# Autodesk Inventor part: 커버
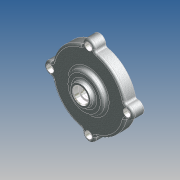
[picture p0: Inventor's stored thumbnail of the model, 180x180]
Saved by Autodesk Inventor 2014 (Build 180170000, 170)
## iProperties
Created: 2012-05
Part Number: 커버
Document SubType Name: 모델링
Designer: SeoGD™
Material: 알루미늄 6061
Appearance: 알루미늄 캐스트
Mass: 72.5671 g
Surface Area: 278.607 cm^2
Volume: 72.5671 cm^3
Density: 1 g/cm^3
변환 표준: STEP AP214IS
파일 이름: C:\Users\SeoGD\Desktop\?쒗뿕\而ㅻ쾭-1.stp
전처리기: Build: 253, Release: 2010 SP1 - Date: Wed 07/29/2009
전송 단위: 밀리미터
불확실성: 0.01
Author: SeoGD™
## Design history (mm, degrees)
sketch "스케치1"
  geometry: L1 (0, 0)-(0, 26); L2 (50, 0)-(50, 15); L3 (50, 15)-(25, 15); L4 (25, 15)-(25, 21); L5 (25, 21)-(15, 21); L6 (15, 21)-(13.66, 26); L7 (13.66, 26)-(10, 26); L8 (50, 0)-(45, 0); L9 (45, 0)-(45, 10); L10 (45, 10)-(14.5, 10); L11 (14.5, 10)-(13.266, 3); L12 (13.266, 3)-(11, 3); L13 (11, 3)-(11, 16); L14 (11, 16)-(7.5, 16); L15 (7.5, 16)-(7.5, 19); L16 (7.5, 19)-(10, 19); L17 (10, 19)-(10, 26)
  constraints: 34 end point, 10 parallel, 2 perpendicular, 2 point on line, 1 vertical
  dimensions: "d11" = 100 diameter of L2 L1; "d12" = 22 diameter of L13 L1; "d13" = 90 diameter of L9 L1; "d14" = 15 distance between parallel lines of L3 L8; "d15" = 10 distance between parallel lines of L8 L10; "d16" = 29 diameter of L10.end L1; "d17" = 100 deg angle of L11 L10; "d18" = 7 distance between parallel lines of L12 L10; "d19" = 13 distance between parallel lines of L14 L12; "d20" = 3 distance between parallel lines of L16 L14; "d21" = 15 diameter of L15 L1; "d22" = 20 diameter of L17 L1; "d23" = 30 diameter of L5.end L1; "d24" = 6 distance between parallel lines of L5 L3; "d25" = 50 diameter of L4 L1; "d26" = 105 deg angle of L5 L6; "d50" = 26 distance of L1.start L1.end
revolve "회전1" sketch "스케치1" stored, may be unused: angle "d27" = 90 deg
sketch "스케치2" dims "d29" = 104
  geometry: A1 r 8.5 centre (0, 52) between (8.074, 49.344) and (-8.074, 49.344); A2 r 50 centre (0, 0) between (-8.074, 49.344) and (8.074, 49.344) reference; 2 further points
  constraints: 4 point on circle, 2 vertical alignment, 1 centre point, 1 coincident, 2 other
  dimensions: "d28" = 17 diameter of A1
extrude "돌출1" join sketch "스케치2" stored distance "d30" = 10; taper "d31" = 0 deg
fillet "모깎기3" dims "d32" = 3
fillet "모깎기4" dims "d45" = 3, "d46" = 0.2
chamfer "모따기1" distance "d47" = 1; stored, may be unused: second distance "d48" = 2, angle "d49" = 45 deg
hole "구멍2" diameter "d38" = 5.5; stored, may be unused: countersink angle "d42" = 90 deg, drill point angle "d44" = 118 deg; dims "d36" = 10, "d37" = 10, "d39" = 6, "d40" = 9.5, "d41" = 5.4, "d43" = 8
node "솔리드1"
node "솔리드 본체"
node "곡면 본체"
pattern_circular "원형 패턴1" dims angle "d34" = 360 deg
pattern_circular "원형 패턴2" dims angle "d52" = 360 deg
node "솔리드2"
